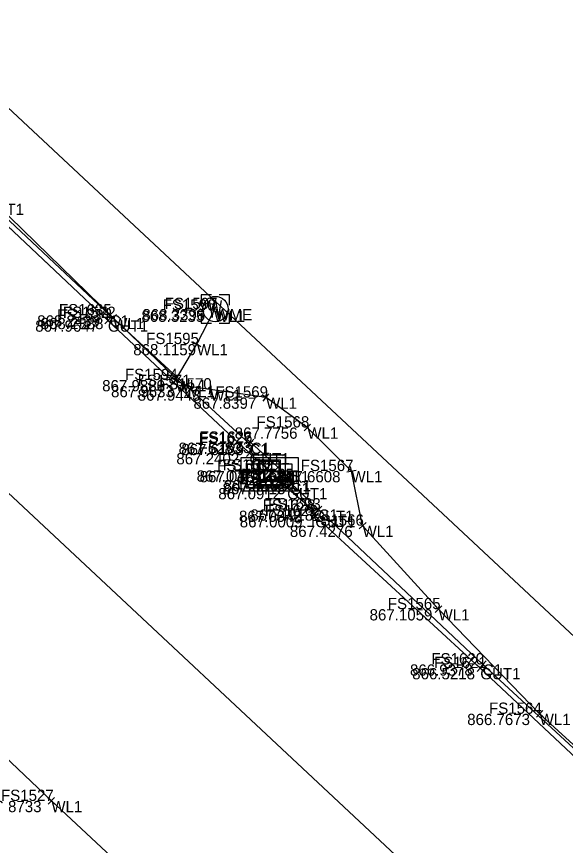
# Model space of a CAD drawing. Extents: x 1469677 to 1493262, y 375219 to 389293.
# Drawn here: x 1479709 to 1479767.4, y 379821.9 to 379910.3 of the extents above; entities that cross this region are included whole.
import ezdxf

# ---------------------------------------------------------------- set-up
doc = ezdxf.new("R2010")
doc.units = 0
for name, color, linetype in [('DR_X_Drive_Pipe', 7, 'Continuous'), ('DV_X_Text', 7, 'Continuous'), ('GK_Visualization', 7, 'Continuous'), ('PNTELEV', 7, 'Continuous'), ('PNTNO', 7, 'Continuous'), ('RD_P_Text', 7, 'Continuous'), ('RW_P_Esmt_SW', 7, 'Continuous'), ('RW_X_CL_20', 7, 'Continuous'), ('SV_X_Mon_Cells_Found', 7, 'Continuous'), ('SV_X_Random_Point', 7, 'Continuous'), ('SV_X_Text_Elevation', 7, 'Continuous')]:
    doc.layers.add(name, color=color, linetype=linetype)

msp = doc.modelspace()

# ---------------------------------------------------------------- linework, layer by layer
at = {"layer": 'DR_X_Drive_Pipe'}
for points in [[(1479473.217, 380054.881), (1479498.741, 380029.974), (1479514.505, 380014.087), (1479533.448, 379996.736), (1479556.003, 379974.32), (1479574.861, 379956.271), (1479584.403, 379947.432), (1479599.597, 379932.82), (1479630.106, 379903.783), (1479644.769, 379889.723), (1479654.209, 379882.356), (1479664.266, 379872.629), (1479692.509, 379845.847), (1479712.672, 379826.686), (1479730.739, 379809.851), (1479753.15, 379788.309), (1479771.842, 379770.542), (1479781.678, 379761.101)], [(1479779.815, 379822.167), (1479764.701, 379835.97), (1479753.929, 379847.124), (1479745.833, 379856.024), (1479744.65, 379861.847), (1479739.947, 379866.491), (1479735.551, 379869.684), (1479729.608, 379870.545), (1479726.79, 379870.913), (1479719.261, 379878.171), (1479705.441, 379891.596), (1479695.924, 379900.162), (1479688.353, 379908.314), (1479682.752, 379913.809)], [(1479725.91, 379871.546), (1479728.18, 379875.382), (1479730.011, 379878.947)]]:
    msp.add_lwpolyline(points, dxfattribs=at)
at = {"layer": 'PNTELEV'}
for p, q in [((1479719.271, 379878.108), (1479718.535, 379878.785)), ((1479718.564, 379878.079), (1479719.242, 379878.814)), ((1479729.566, 379879.176), (1479730.456, 379878.719)), ((1479729.783, 379878.502), (1479730.239, 379879.392)), ((1479730.011, 379878.947), (1479730.011, 379878.947)), ((1479719.066, 379877.556), (1479718.336, 379878.24)), ((1479718.359, 379877.533), (1479719.043, 379878.263)), ((1479718.701, 379877.898), (1479718.701, 379877.898)), ((1479719.621, 379877.824), (1479718.901, 379878.518)), ((1479718.903, 379878.447), (1479718.903, 379878.447)), ((1479718.914, 379877.811), (1479719.608, 379878.531)), ((1479719.261, 379878.171), (1479719.261, 379878.171)), ((1479727.75, 379875.636), (1479728.61, 379875.127)), ((1479727.925, 379874.951), (1479728.435, 379875.812)), ((1479728.18, 379875.382), (1479728.18, 379875.382)), ((1479725.48, 379871.801), (1479726.34, 379871.291)), ((1479725.655, 379871.116), (1479726.165, 379871.976)), ((1479725.91, 379871.546), (1479725.91, 379871.546)), ((1479727.286, 379870.848), (1479726.294, 379870.978)), ((1479726.725, 379870.417), (1479726.855, 379871.409)), ((1479726.79, 379870.913), (1479726.79, 379870.913)), ((1479729.536, 379870.05), (1479729.68, 379871.039)), ((1479730.103, 379870.473), (1479729.113, 379870.616)), ((1479729.608, 379870.545), (1479729.608, 379870.545)), ((1479735.956, 379869.39), (1479735.146, 379869.978)), ((1479735.257, 379869.28), (1479735.845, 379870.089)), ((1479735.551, 379869.684), (1479735.551, 379869.684)), ((1479740.303, 379866.139), (1479739.591, 379866.842)), ((1479739.596, 379866.135), (1479740.298, 379866.846)), ((1479739.947, 379866.491), (1479739.947, 379866.491)), ((1479734.151, 379865.066), (1479733.389, 379864.42)), ((1479734.093, 379864.362), (1479733.447, 379865.125)), ((1479734.295, 379864.538), (1479733.557, 379865.212)), ((1479733.589, 379864.506), (1479734.263, 379865.245)), ((1479733.77, 379864.743), (1479733.77, 379864.743)), ((1479733.926, 379864.875), (1479733.926, 379864.875)), ((1479734.155, 379863.425), (1479733.419, 379864.101)), ((1479733.449, 379863.395), (1479734.125, 379864.132)), ((1479733.787, 379863.763), (1479733.787, 379863.763)), ((1479736.235, 379861.51), (1479735.505, 379862.193)), ((1479735.528, 379861.487), (1479736.212, 379862.217)), ((1479744.16, 379861.747), (1479745.14, 379861.946)), ((1479744.75, 379861.357), (1479744.55, 379862.337)), ((1479735.87, 379861.852), (1479735.87, 379861.852)), ((1479737.83, 379861.083), (1479738.754, 379860.702)), ((1479738.102, 379860.43), (1479738.482, 379861.355)), ((1479744.65, 379861.847), (1479744.65, 379861.847)), ((1479738.186, 379859.71), (1479737.43, 379860.365)), ((1479737.481, 379859.66), (1479738.135, 379860.416)), ((1479738.525, 379860.233), (1479737.799, 379860.92)), ((1479737.818, 379860.213), (1479738.506, 379860.939)), ((1479738.162, 379860.576), (1479738.162, 379860.576)), ((1479738.292, 379860.893), (1479738.292, 379860.893)), ((1479737.808, 379860.038), (1479737.808, 379860.038)), ((1479740.121, 379857.458), (1479741.063, 379857.794)), ((1479740.76, 379857.155), (1479740.424, 379858.097)), ((1479740.592, 379857.626), (1479740.592, 379857.626)), ((1479741.507, 379857.412), (1479740.779, 379858.098)), ((1479740.8, 379857.391), (1479741.486, 379858.119)), ((1479741.143, 379857.755), (1479741.143, 379857.755)), ((1479741.168, 379856.703), (1479740.432, 379857.381)), ((1479740.461, 379856.674), (1479741.139, 379857.41)), ((1479740.8, 379857.042), (1479740.8, 379857.042)), ((1479745.463, 379855.687), (1479746.203, 379856.36)), ((1479746.169, 379855.654), (1479745.497, 379856.393)), ((1479745.833, 379856.024), (1479745.833, 379856.024)), ((1479753.569, 379846.777), (1479754.289, 379847.471)), ((1479754.276, 379846.764), (1479753.582, 379847.484)), ((1479753.929, 379847.124), (1479753.929, 379847.124)), ((1479758.312, 379840.87), (1479758.99, 379841.605)), ((1479758.743, 379840.503), (1479758.013, 379841.187)), ((1479758.036, 379840.48), (1479758.72, 379841.21)), ((1479759.018, 379840.898), (1479758.284, 379841.577)), ((1479758.378, 379840.845), (1479758.378, 379840.845)), ((1479758.651, 379841.238), (1479758.651, 379841.238)), ((1479765.07, 379835.633), (1479764.332, 379836.307)), ((1479764.364, 379835.601), (1479765.038, 379836.339)), ((1479764.701, 379835.97), (1479764.701, 379835.97)), ((1479712.31, 379827.031), (1479713.034, 379826.342)), ((1479713.016, 379827.049), (1479712.328, 379826.324)), ((1479712.672, 379826.686), (1479712.672, 379826.686))]:
    msp.add_line(p, q, dxfattribs=at)
at = {"layer": 'PNTNO'}
msp.add_line((1479730.153, 379879.115), (1479730.153, 379879.115), dxfattribs=at)
for points in [[(1479729.753, 379880.615), (1479728.653, 379880.615), (1479728.653, 379879.515)], [(1479731.653, 379879.515), (1479731.653, 379880.615), (1479730.553, 379880.615)], [(1479729.486, 379880.015), (1479729.82, 379878.215), (1479730.153, 379880.015), (1479730.486, 379878.215), (1479730.82, 379880.015)], [(1479728.653, 379878.715), (1479728.653, 379877.615), (1479729.753, 379877.615)], [(1479730.553, 379877.615), (1479731.653, 379877.615), (1479731.653, 379878.715)]]:
    msp.add_lwpolyline(points, dxfattribs=at)
msp.add_circle((1479730.153, 379879.115), 1.35, dxfattribs=at)
at = {"layer": 'RD_P_Text'}
for points in [[(1479775.464, 379824.819), (1479758.378, 379840.845), (1479740.8, 379857.042), (1479740.592, 379857.626), (1479737.808, 379860.038), (1479735.87, 379861.852), (1479733.787, 379863.763), (1479718.701, 379877.898), (1479705.478, 379890.334), (1479700.95, 379894.575), (1479699.048, 379897.264), (1479697.778, 379899.5), (1479696.445, 379902.732), (1479695.776, 379905.397), (1479695.475, 379907.419), (1479695.142, 379911.531)], [(1479775.613, 379825.569), (1479758.651, 379841.238), (1479741.143, 379857.755), (1479738.162, 379860.576), (1479738.292, 379860.893), (1479733.926, 379864.875), (1479733.77, 379864.743), (1479718.903, 379878.447), (1479705.833, 379890.72), (1479701.383, 379894.845), (1479699.526, 379897.552), (1479698.177, 379899.762), (1479696.913, 379902.812), (1479696.188, 379905.546), (1479696.149, 379907.481), (1479695.686, 379911.644)]]:
    msp.add_lwpolyline(points, dxfattribs=at)
at = {"layer": 'RW_X_CL_20'}
for p, q in [((1479735.918, 379863.58), (1479735.918, 379863.58)), ((1479735.918, 379862.913), (1479735.918, 379862.913)), ((1479735.93, 379863.28), (1479735.93, 379863.28)), ((1479735.93, 379862.614), (1479735.93, 379862.614)), ((1479733.555, 379861.489), (1479733.555, 379861.489)), ((1479734.918, 379861.913), (1479734.918, 379861.913)), ((1479735.918, 379861.913), (1479735.918, 379861.913)), ((1479735.918, 379861.913), (1479735.918, 379861.913)), ((1479735.918, 379861.913), (1479735.918, 379861.913)), ((1479735.93, 379861.864), (1479735.93, 379861.864)), ((1479735.93, 379861.864), (1479735.93, 379861.864)), ((1479735.93, 379861.489), (1479735.93, 379861.489)), ((1479736.918, 379861.913), (1479736.918, 379861.913)), ((1479738.305, 379861.489), (1479738.305, 379861.489)), ((1479735.918, 379860.913), (1479735.918, 379860.913)), ((1479735.918, 379860.246), (1479735.918, 379860.246)), ((1479735.93, 379860.364), (1479735.93, 379860.364)), ((1479735.93, 379859.697), (1479735.93, 379859.697))]:
    msp.add_line(p, q, dxfattribs=at)
at = {"layer": 'SV_X_Mon_Cells_Found'}
msp.add_lwpolyline([(1477206.544, 382340.781), (1479657.335, 379947.979), (1480466.338, 379191.878)], dxfattribs=at)
at = {"layer": 'SV_X_Random_Point'}
for p, q in [((1479734.772, 379861.3), (1479736.531, 379863.059)), ((1479734.772, 379862.431), (1479735.4, 379863.059)), ((1479735.371, 379860.767), (1479737.064, 379862.46)), ((1479733.43, 379860.105), (1479735.184, 379861.864)), ((1479733.43, 379861.238), (1479734.054, 379861.864)), ((1479734.486, 379860.03), (1479736.314, 379861.864)), ((1479735.615, 379860.03), (1479737.444, 379861.864)), ((1479736.502, 379860.767), (1479737.064, 379861.329)), ((1479736.745, 379860.03), (1479738.43, 379861.72)), ((1479737.875, 379860.03), (1479738.43, 379860.587))]:
    msp.add_line(p, q, dxfattribs=at)
for points in [[(1479732.888, 379863.281), (1479738.972, 379863.281), (1479738.972, 379859.697), (1479732.888, 379859.697)], [(1479734.251, 379863.58), (1479737.585, 379863.58), (1479737.585, 379860.246), (1479734.251, 379860.246)], [(1479734.772, 379863.059), (1479737.064, 379863.059), (1479737.064, 379860.767), (1479734.772, 379860.767)], [(1479734.918, 379862.913), (1479736.918, 379862.913), (1479736.918, 379860.913), (1479734.918, 379860.913)], [(1479733.555, 379862.614), (1479738.305, 379862.614), (1479738.305, 379860.364), (1479733.555, 379860.364)], [(1479733.43, 379861.864), (1479738.43, 379861.864), (1479738.43, 379860.03), (1479733.43, 379860.03)]]:
    msp.add_lwpolyline(points, close=True, dxfattribs=at)
at = {"layer": 'SV_X_Text_Elevation'}
msp.add_line((1479636.611, 379926.284), (1480557.828, 379065.308), dxfattribs=at)

# ---------------------------------------------------------------- texts
at = {"layer": 'DV_X_Text'}
for s, height, p in [('868.3235', 1.2, (1479722.273, 379877.747)), ('868.3398', 1.2, (1479722.368, 379877.915)), ('867.9647', 1.2, (1479710.954, 379876.698)), ('868.2439', 1.2, (1479711.165, 379877.247)), ('868.2388', 1.2, (1479711.532, 379876.971)), ('868.1159', 1.2, (1479721.397, 379874.182)), ('867.9880', 1.2, (1479718.087, 379870.346)), ('867.9633', 1.2, (1479719.033, 379869.713)), ('867.9443', 1.2, (1479721.87, 379869.345)), ('867.8397', 1.2, (1479727.813, 379868.484)), ('867.7756', 1.2, (1479732.209, 379865.291)), ('867.6283', 1.2, (1479726.226, 379863.675)), ('867.6189', 1.2, (1479726.514, 379863.543)), ('867.2402', 1.2, (1479725.992, 379862.563)), ('867.0774', 1.2, (1479728.152, 379860.713)), ('867.0361', 1.2, (1479728.47, 379860.652)), ('867.0201', 0.2, (1479734.687, 379861.664)), ('867.6608', 1.2, (1479736.789, 379860.647)), ('867.4413', 1.2, (1479730.916, 379859.376)), ('867.4162', 1.2, (1479731.046, 379859.693)), ('867.0912', 1.2, (1479730.458, 379858.838)), ('867.0042', 1.2, (1479732.665, 379856.426)), ('867.4918', 1.2, (1479733.878, 379856.555)), ('867.0009', 1.2, (1479732.75, 379855.842)), ('867.4276', 1.2, (1479738.086, 379854.824)), ('867.1059', 1.2, (1479746.579, 379845.924)), ('866.9378', 1.2, (1479750.885, 379840.038)), ('866.5218', 1.2, (1479751.122, 379839.645)), ('866.7673', 1.2, (1479756.982, 379834.77)), ('866.8733', 1.2, (1479704.934, 379825.486))]:
    msp.add_text(s, height=height, dxfattribs=at).set_placement(p)
at = {"layer": 'GK_Visualization'}
for s, height, p in [('GUT1', 1.2, (1479705.478, 379889.134)), ('WL1', 1.2, (1479730.011, 379877.747)), ('WME', 1.2, (1479730.153, 379877.915)), ('GUT1', 1.2, (1479718.701, 379876.698)), ('C1', 1.2, (1479718.903, 379877.247)), ('WL1', 1.2, (1479719.261, 379876.971)), ('WL1', 1.2, (1479728.18, 379874.182)), ('WL1', 1.2, (1479725.91, 379870.346)), ('WL1', 1.2, (1479726.79, 379869.713)), ('WL1', 1.2, (1479729.608, 379869.345)), ('WL1', 1.2, (1479735.551, 379868.484)), ('WL1', 1.2, (1479739.947, 379865.291)), ('C1', 1.2, (1479733.77, 379863.543)), ('C1', 1.2, (1479733.926, 379863.675)), ('GUT1', 1.2, (1479733.787, 379862.563)), ('CBS', 1.2, (1479735.918, 379860.713)), ('CB-3', 0.2, (1479735.93, 379861.664)), ('GUT1', 1.2, (1479735.87, 379860.652)), ('WL1', 1.2, (1479744.65, 379860.647)), ('C1', 1.2, (1479738.162, 379859.376)), ('C1', 1.2, (1479738.292, 379859.693)), ('GUT1', 1.2, (1479737.808, 379858.838)), ('GUT1', 1.2, (1479740.592, 379856.426)), ('C1', 1.2, (1479741.143, 379856.555)), ('GUT1', 1.2, (1479740.8, 379855.842)), ('WL1', 1.2, (1479745.833, 379854.824)), ('WL1', 1.2, (1479753.929, 379845.924)), ('GUT1', 1.2, (1479758.378, 379839.645)), ('C1', 1.2, (1479758.651, 379840.038)), ('WL1', 1.2, (1479764.701, 379834.77)), ('WL1', 1.2, (1479712.672, 379825.486))]:
    msp.add_text(s, height=height, dxfattribs=at).set_placement(p)
at = {"layer": 'RW_P_Esmt_SW'}
for s, height, p in [('FS1635', 1.2, (1479713.48, 379878.447)), ('FS1596', 1.2, (1479724.532, 379878.947)), ('FS1597', 1.2, (1479724.749, 379879.115)), ('FS1634', 1.2, (1479713.288, 379877.898)), ('FS1572', 1.2, (1479713.905, 379878.171)), ('FS1595', 1.2, (1479722.776, 379875.382)), ('FS1594', 1.2, (1479720.516, 379871.546)), ('FS1571', 1.2, (1479721.875, 379870.913)), ('FS1570', 1.2, (1479724.138, 379870.545)), ('FS1569', 1.2, (1479730.138, 379869.684)), ('FS1568', 1.2, (1479734.534, 379866.491)), ('FS1627', 1.2, (1479728.385, 379864.743)), ('FS1626', 1.2, (1479728.466, 379864.875)), ('FS1633', 1.2, (1479728.364, 379863.763)), ('FS1630', 1.2, (1479730.343, 379861.852)), ('FS1631', 1.2, (1479730.947, 379861.913)), ('FS1567', 1.2, (1479739.246, 379861.847)), ('FS1625', 1.2, (1479732.907, 379860.893)), ('FS1632', 0.2, (1479735.028, 379861.864)), ('FS1629', 1.2, (1479732.414, 379860.038)), ('FS1624', 1.2, (1479732.787, 379860.576)), ('FS1628', 1.2, (1479735.198, 379857.626)), ('FS1623', 1.2, (1479735.758, 379857.755)), ('FS1622', 1.2, (1479735.425, 379857.042)), ('FS1566', 1.2, (1479740.354, 379856.024)), ('FS1565', 1.2, (1479748.525, 379847.124)), ('FS1620', 1.2, (1479753.162, 379841.238)), ('FS1621', 1.2, (1479753.444, 379840.845)), ('FS1564', 1.2, (1479759.307, 379835.97)), ('FS1527', 1.2, (1479707.306, 379826.686))]:
    msp.add_text(s, height=height, dxfattribs=at).set_placement(p)

doc.saveas('drawing.dxf')
